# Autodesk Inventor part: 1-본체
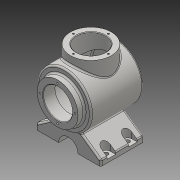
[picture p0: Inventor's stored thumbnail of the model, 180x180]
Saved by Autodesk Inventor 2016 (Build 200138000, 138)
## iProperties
Created: 2017-04
Part Number: 1-본체
Material: 일반
Document SubType Name: Modeling
Designer: H
Density: 1 g/cm^3
Appearance: 기본값
Author: H
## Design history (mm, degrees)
sketch "스케치2"
  geometry: L1 (-54, 50)-(54, 50); L2 (54, 50)-(54, 0); L3 (54, 0)-(-54, 0); L4 (-54, 0)-(-54, 50); A1 r 113 centre (-59, 0) between (54, 0) and (42.336, 50); 2 further points
  constraints: 8 end point, 2 parallel, 2 point on circle, 2 point on line, 1 centre point, 1 coincident, 1 horizontal, 1 midpoint, 1 perpendicular
  dimensions: "d0" = 108 distance of L1.start L1.end; "d1" = 113 radius of A1; "d2" = 100 diameter of L1 L3
revolve "회전1" sketch "스케치2" stored, may be unused: angle "d3" = 90 deg
node "작업 평면1"
sketch "스케치4"
  geometry: L1 (50, -54)-(-50, -54) reference; C1 r 38 at (0, -4); 2 further points
  constraints: 1 centre point, 1 midpoint, 1 vertical alignment
  dimensions: "d8" = 50 distance from line of L1 C1.centre; "d9" = 76 diameter of C1
extrude "돌출2" join sketch "스케치4" stored distance "d10" = 10; taper "d11" = 0 deg
sketch "스케치5"
  geometry: C1 r 38 at (0, 0); C2 r 50 at (0, 0) reference; 1 further point
  constraints: 1 centre point, 1 coincident
  dimensions: "d12" = 76 diameter of C1
extrude "돌출3" join sketch "스케치5" distance "d13" = 12; taper "d14" = 0 deg
node "작업 평면2"
sketch "스케치6"
  geometry: L1 (-60, -72)-(60, -72); L2 (60, -72)-(60, -82); L3 (60, -82)-(-60, -82); L4 (-60, -82)-(-60, -72); L5 (-60, -72)-(-5.876, -34.102); L6 (-5.876, -34.102)-(5.876, -34.102); L7 (5.876, -34.102)-(60, -72); C1 r 50 at (0, 0) reference; 2 further points
  constraints: 14 end point, 2 horizontal, 2 parallel, 1 equal length, 1 midpoint, 1 perpendicular, 1 vertical alignment
  dimensions: "d16" = 10 distance of L1.end L2.end; "d17" = 82 distance from line of point (0, 0) L3; "d18" = 120 distance of L2.end L3.end; "d19" = 55 deg angle of L4 L5; "d20" = 37.89801 distance between parallel lines of L1 L6
extrude "돌출4" join sketch "스케치6" distance "d21" = 80; taper "d22" = 0 deg
sketch "스케치7"
  geometry: L1 (-54, 50)-(42.336, 50) reference; L2 (-54, -50)-(42.336, -50) reference; L3 (-54, -50)-(-54, 50) reference; L4 (-44, 0)-(54, 0); L5 (35.916, 40)-(-44, 40); L6 (-44, 40)-(-44, 0); A1 r 113 centre (-59, 0) between (42.336, -50) and (42.336, 50) reference; A2 r 103 centre (-59, 0) between (44, 0) and (35.916, 40); 1 further point
  constraints: 7 end point, 4 point on circle, 2 point on line, 1 centre point, 1 other
  dimensions: "d24" = 10 distance between parallel lines of L1 L5; "d25" = 10 radial gap between concentric circles of A1 A2; "d26" = 98 distance of L4.start L4.end
revolve "회전2" sketch "스케치7" stored, may be unused: angle "d27" = 90 deg
hole "구멍1" diameter "d30" = 54; stored, may be unused: countersink angle "d34" = 90 deg, drill point angle "d36" = 118 deg; dims "d28" = 10, "d29" = 10, "d31" = 6, "d32" = 4, "d33" = 2, "d35" = 8
hole "구멍2" diameter "d39" = 54; stored, may be unused: countersink angle "d43" = 90 deg, drill point angle "d45" = 118 deg; dims "d37" = 10, "d38" = 10, "d40" = 6, "d41" = 4, "d42" = 2, "d44" = 8
sketch "스케치8"
  geometry: L1 (0, 0)-(0, -32.5); C1 r 38 at (0, 0) reference; 1 further point
  constraints: 2 end point, 1 vertical
  dimensions: "d46" = 32.5 distance of L1.start L1.end
hole "구멍3" sketch "스케치8" at (0, -32.5) diameter "d47" = 3.242; stored, may be unused: countersink angle "d51" = 90 deg, drill point angle "d53" = 118 deg; dims "d48" = 8, "d49" = 4, "d50" = 2, "d52" = 10
sketch "스케치9"
  geometry: L1 (0, 0)-(0, 32.5); C1 r 38 at (0, 0) reference; 1 further point
  constraints: 2 end point, 1 vertical
  dimensions: "d57" = 32.5 distance of L1.start L1.end
hole "구멍4" sketch "스케치9" at (0, 32.5) diameter "d58" = 3.242; stored, may be unused: countersink angle "d62" = 90 deg, drill point angle "d64" = 118 deg; dims "d59" = 8, "d60" = 4, "d61" = 2, "d63" = 10
sketch "스케치10"
  geometry: L1 (-60, -82)-(60, -82) reference; C1 r 18 at (0, -82); 1 further point
  constraints: 1 centre point, 1 midpoint
  dimensions: "d69" = 18 radius of C1
extrude "돌출5" cut sketch "스케치10" stored distance "d70" = 80; taper "d71" = 0 deg
node "작업 평면3"
sketch "스케치11"
  geometry: L1 (60, -46)-(60, 34) reference; L2 (18, -46)-(-18, -46) reference; L3 (50, 14)-(-50, 14); L4 (-50, 14)-(-50, -26); L5 (-50, -26)-(50, -26); L6 (50, -26)-(50, 14); L7 (-50, 14)-(-60, 14); L8 (-50, 22)-(-60, 22); L9 (-60, 6)-(-50, 6); L10 (-60, -46)-(-60, 34) reference; L11 (-50, -26)-(-60, -26); L12 (-50, -18)-(-60, -18); L13 (-60, -34)-(-50, -34); L14 (50, 14)-(60, 14); L15 (50, 6)-(60, 6); L16 (60, 22)-(50, 22); L17 (50, -26)-(60, -26); L18 (50, -34)-(60, -34); L19 (60, -18)-(50, -18); A1 r 8 centre (-50, 14) between (-50, 6) and (-50, 22); A2 r 8 centre (-60, 14) between (-60, 22) and (-60, 6); A3 r 8 centre (-50, -26) between (-50, -34) and (-50, -18); A4 r 8 centre (-60, -26) between (-60, -18) and (-60, -34); A5 r 8 centre (50, 14) between (50, 22) and (50, 6); A6 r 8 centre (60, 14) between (60, 6) and (60, 22); A7 r 8 centre (50, -26) between (50, -18) and (50, -34); A8 r 8 centre (60, -26) between (60, -34) and (60, -18); 9 further points
  constraints: 40 end point, 16 point on circle, 16 tangent, 8 centre point, 8 midpoint, 7 point on line, 6 parallel, 2 horizontal, 1 horizontal alignment, 1 perpendicular, 1 vertical alignment
  dimensions: "d73" = 40 distance of L5.end L3.start; "d74" = 100 distance of L4.end L5.end; "d75" = 8 radius of A2; "d76" = 8 radius of A4; "d77" = 8 radius of A6; "d78" = 8 radius of A8
extrude "돌출6" cut sketch "스케치11" distance "d79" = 24.75; taper "d80" = 0 deg
hole "구멍5" diameter "d83" = 8; stored, may be unused: countersink angle "d87" = 90 deg, drill point angle "d89" = 118 deg; dims "d81" = 10, "d82" = 10, "d84" = 8, "d85" = 4, "d86" = 2, "d88" = 10
hole "구멍6" diameter "d92" = 8; stored, may be unused: countersink angle "d96" = 90 deg, drill point angle "d98" = 118 deg; dims "d90" = 10, "d91" = 10, "d93" = 8, "d94" = 4, "d95" = 2, "d97" = 10
hole "구멍7" diameter "d101" = 8; stored, may be unused: countersink angle "d105" = 90 deg, drill point angle "d107" = 118 deg; dims "d99" = 10, "d100" = 10, "d102" = 8, "d103" = 4, "d104" = 2, "d106" = 10
hole "구멍8" diameter "d110" = 8; stored, may be unused: countersink angle "d114" = 90 deg, drill point angle "d116" = 118 deg; dims "d108" = 10, "d109" = 10, "d111" = 8, "d112" = 4, "d113" = 2, "d115" = 10
node "작업 평면4"
sketch "스케치12"
  geometry: C1 r 50 at (0, 0) reference; 2 further points
  constraints: 1 coincident, 1 other
feature "엠보싱1" sketch "스케치12" dims "d118" = 0.5, "d119" = 0
fillet "모깎기1" dims "d120" = 3
chamfer "모따기1" distance "d121" = 1; stored, may be unused: second distance "d122" = 2, angle "d123" = 45 deg
fillet "모깎기2" dims "d124" = 3
fillet "모깎기3" dims "d125" = 3
fillet "모깎기4" dims "d126" = 3
fillet "모깎기5" dims "d127" = 3
node "솔리드1"
pattern_circular "원형 패턴1" dims angle "d55" = 360 deg
pattern_circular "원형 패턴2" dims angle "d66" = 360 deg
other parameters: "d4" = 65, "d15" = -8, "d72" = -51.25, "d117" = 82.5
